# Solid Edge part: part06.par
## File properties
Author: Robert a Rhodes jr
Template: normal.par
Last saved by: TIET
Revision: 9
Application: Solid Edge
Accuracy: 0.99
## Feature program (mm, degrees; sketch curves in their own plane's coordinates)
sketch for "unnamed Protrusion 1" plane through (0, 0, 0) normal (0, -1, 0) x-axis (1, 0, 0)
  arc centre (60, 0) radius 30 from (60, 30) to (60, -30) cw
  line (104, -30) -> (60, -30)
  line (104, 18) -> (104, -30)
  line (164, 18) -> (104, 18)
  line (164, -4) -> (164, 18)
  line (182, -4) -> (164, -4)
  line (182, -4) -> (182, 36)
  line (142, 36) -> (182, 36)
  line (142, 30) -> (142, 36)
  line (60, 30) -> (142, 30)
extrude "unnamed Protrusion 1" add finite 54 symmetric
sketch for "ExtrudedProtrusion_6" #1 plane through (0, 0, 0) normal (0, -1, 0) x-axis (1, 0, 0)
  arc centre (60, 0) radius 30 from (60, 30) to (60, -30) ccw
  arc centre (60, 0) radius 30 from (60, 30) to (60, -30) cw
sketch for "ExtrudedProtrusion_6" #2 plane through (0, 0, 0) normal (0, -1, 0) x-axis (1, 0, 0)
  circle centre (60, 0) radius 18
extrude "ExtrudedProtrusion_6" add finite 66 symmetric
sketch for "ExtrudedProtrusion_7" plane through (0, 0, 0) normal (0, -1, 0) x-axis (1, 0, 0)
  line (104, -30) -> (164, -4)
  line (164, -4) -> (164, 18)
  line (164, 18) -> (104, 18)
  line (104, 18) -> (104, -30)
extrude "ExtrudedProtrusion_7" add finite 18 symmetric
sketch for "ExtrudedProtrusion_8" plane through (0, 0, 0) normal (0, -1, 0) x-axis (1, 0, 0)
  line (200, 76) -> (200, -4)
  line (200, -4) -> (182, -4)
  line (182, -4) -> (182, 36)
  line (182, 76) -> (182, 36)
  line (182, 76) -> (200, 76)
extrude "ExtrudedProtrusion_8" add finite 92 symmetric
sketch for "ExtrudedProtrusion_9" plane through (0, 0, 0) normal (0, -1, 0) x-axis (1, 0, 0)
  line (142, 36) -> (182, 76)
  line (182, 76) -> (182, 36)
  line (142, 36) -> (182, 36)
extrude "ExtrudedProtrusion_9" add finite 12 symmetric
sketch for "unnamed Hole 1" plane through (200, 0, 36) normal (1, 0, 0) x-axis (0, 1, 0)
hole "unnamed Hole 1" through
sketch for "Hole_1" plane through (200, 0, 36) normal (1, 0, 0) x-axis (0, 1, 0)
  hole centre (-30, 22) bore radius 8
hole "Hole_1" diameter 16 through
pattern "unnamed Pattern 1" of "unnamed Hole 1", "Hole_1"
fillet "unnamed Round 1"
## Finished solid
Body 1: solid body, 34 faces, 81 edges, 46 vertices.
  Faces by surface: plane 28, cylinder 6
  Edges by curve: line 67, circle 14
Bounding box of the edges (mm): 170.000 x 92.000 x 106.000, from (30, -46, -30) to (200, 46, 76).
Cylindrical faces by radius (mm): R8 x2, R16 x2, R18 x1, R30 x1
Planar faces by outward normal: +x 3, +y 5, +z 4, -x 5, -y 5, -z 4, oblique 2
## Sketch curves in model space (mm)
circle centre (60, 0, 0) radius 18
line (182, 0, -4) -> (164, 0, -4)
line (104, 0, -30) -> (60, 0, -30)
arc centre (60, 0, 0) radius 30 from (60, 0, 30) through (30.0132, 0, -0.889) to (60, 0, -30)
arc centre (60, 0, 0) radius 30 from (60, 0, 30) through (89.9868, 0, -0.889) to (60, 0, -30)
line (142, 0, 36) -> (182, 0, 76)
line (142, 0, 36) -> (182, 0, 36)
line (104, 0, -30) -> (164, 0, -4)
line (182, 0, 76) -> (182, 0, 36)
line (182, 0, -4) -> (182, 0, 36)
line (142, 0, 30) -> (142, 0, 36)
line (60, 0, 30) -> (142, 0, 30)
line (104, 0, 18) -> (104, 0, -30)
line (164, 0, 18) -> (104, 0, 18)
line (164, 0, -4) -> (164, 0, 18)
line (200, 0, -4) -> (182, 0, -4)
line (200, 0, 76) -> (200, 0, -4)
line (182, 0, 76) -> (200, 0, 76)
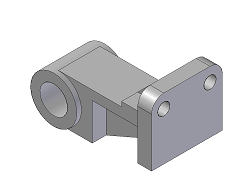
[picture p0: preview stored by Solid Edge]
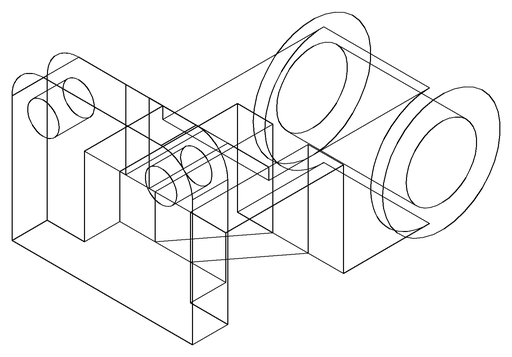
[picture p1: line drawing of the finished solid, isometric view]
